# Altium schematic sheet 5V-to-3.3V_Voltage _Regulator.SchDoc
size 431 x 279 mm; Organization: ORGANIZATION; Address1: ADDRESS 1; Address2: ADDRESS 2; Address3: ADDRESS 3; Address4: ADDRESS 4; Revision: -; SheetNumber: 1; SheetTotal: 4; ENG_APP_DATE: --/--/--; DSN_APP_DATE: --/--/--; CHK_APP_DATE: --/--/--
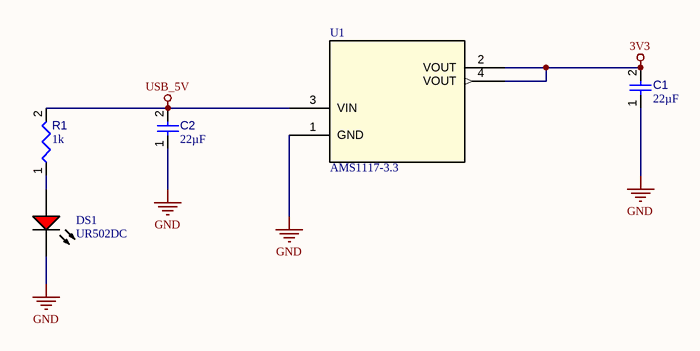
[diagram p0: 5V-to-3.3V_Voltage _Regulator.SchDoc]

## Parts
C1  value 22µF  [CAPC0805(2012)145_L]  (hidden comment: Capacitor 22µF +/-40% 16V 0805)
C2  value 22µF  [CAPC0805(2012)145_L]  (hidden comment: Capacitor 22µF +/-40% 16V 0805)
DS1  UR502DC  [CGX-UR502DC]
R1  value 1k  [RESC0805(2012)_L]  (hidden comment: Resistor 1K +/-5% 0805 125 mW)
U1  AMS1117-3.3  [SOT-223_UMW]

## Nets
3V3: C1.2 U1.2(VOUT) U1.4(VOUT)
GND: C1.1 C2.1 DS1.2(K) U1.1(GND)
USB_5V: C2.2 R1.2 U1.3(VIN)
NetDS1_1: DS1.1(A) R1.1

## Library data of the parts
C1 C2 = CMP-001-00081-4: Chip Capacitor, 22µF +/-40%, 16V, 0805, Thickness 1.45 mm; Tolerance: 5%
DS1 = CMP-007-00009-2: Red LED, 80 mW, 30 mA, -25 to 85 degC, 2-Pin THD; Manufacturer: Shenzhen CGX; Power: 80mW
R1 = CMP-009-00118-3: Chip Resistor, 1 kOhms, +/-5%, 125 mW, -55 to 155 degC, 0805; Tolerance: 5%; Power: 125mW
U1 = AMS1117-3.3: Description; Manufacturer_Name: UMW(Youtai Semiconductor Co., Ltd.)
